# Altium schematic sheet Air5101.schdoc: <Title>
size 419 x 266 mm; Name: SIZEB; Symbol: SIZEB; Device: SIZEB; Drawn By: <Drawn By>; Checked By: <Checked By>; QC By: <QC By>; Released By: <Released By>; Drawn Date: <Drawn Date>; Checked Date: <Checked Date>; QC Date: <QC Date>; Release Date: <Release Date>; Company Name: <Company Name>; Code: <Code>; Sheet Size: B; Drawing Number: <Drawing Number>; Revision: <Revision>; Scale: <Scale>; Sheet Number: 1; Number of Sheets: 1
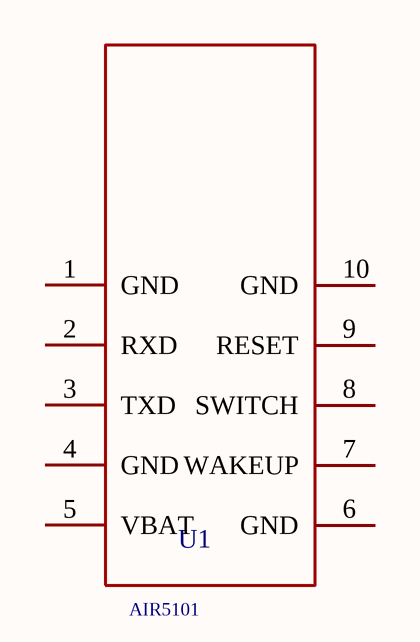
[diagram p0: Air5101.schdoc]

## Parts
U1  AIR5101

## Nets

Not connected (* = marked no-connect by the designer): U1 1(GND) 2(RXD) 3(TXD) 4(GND) 5(VBAT) 6(GND) 7(WAKEUP) 8(SWITCH) 9(RESET) 10(GND)

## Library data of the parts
U1 = AIR5101: Add into BOM: yes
